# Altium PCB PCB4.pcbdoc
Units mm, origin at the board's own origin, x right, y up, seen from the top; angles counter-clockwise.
Board outline 77.7 x 78.7 mm, 4 copper layers (Top Layer, GND, VCC, Bottom Layer); 33 components, 18 nets, 107 pads, 174 vias.
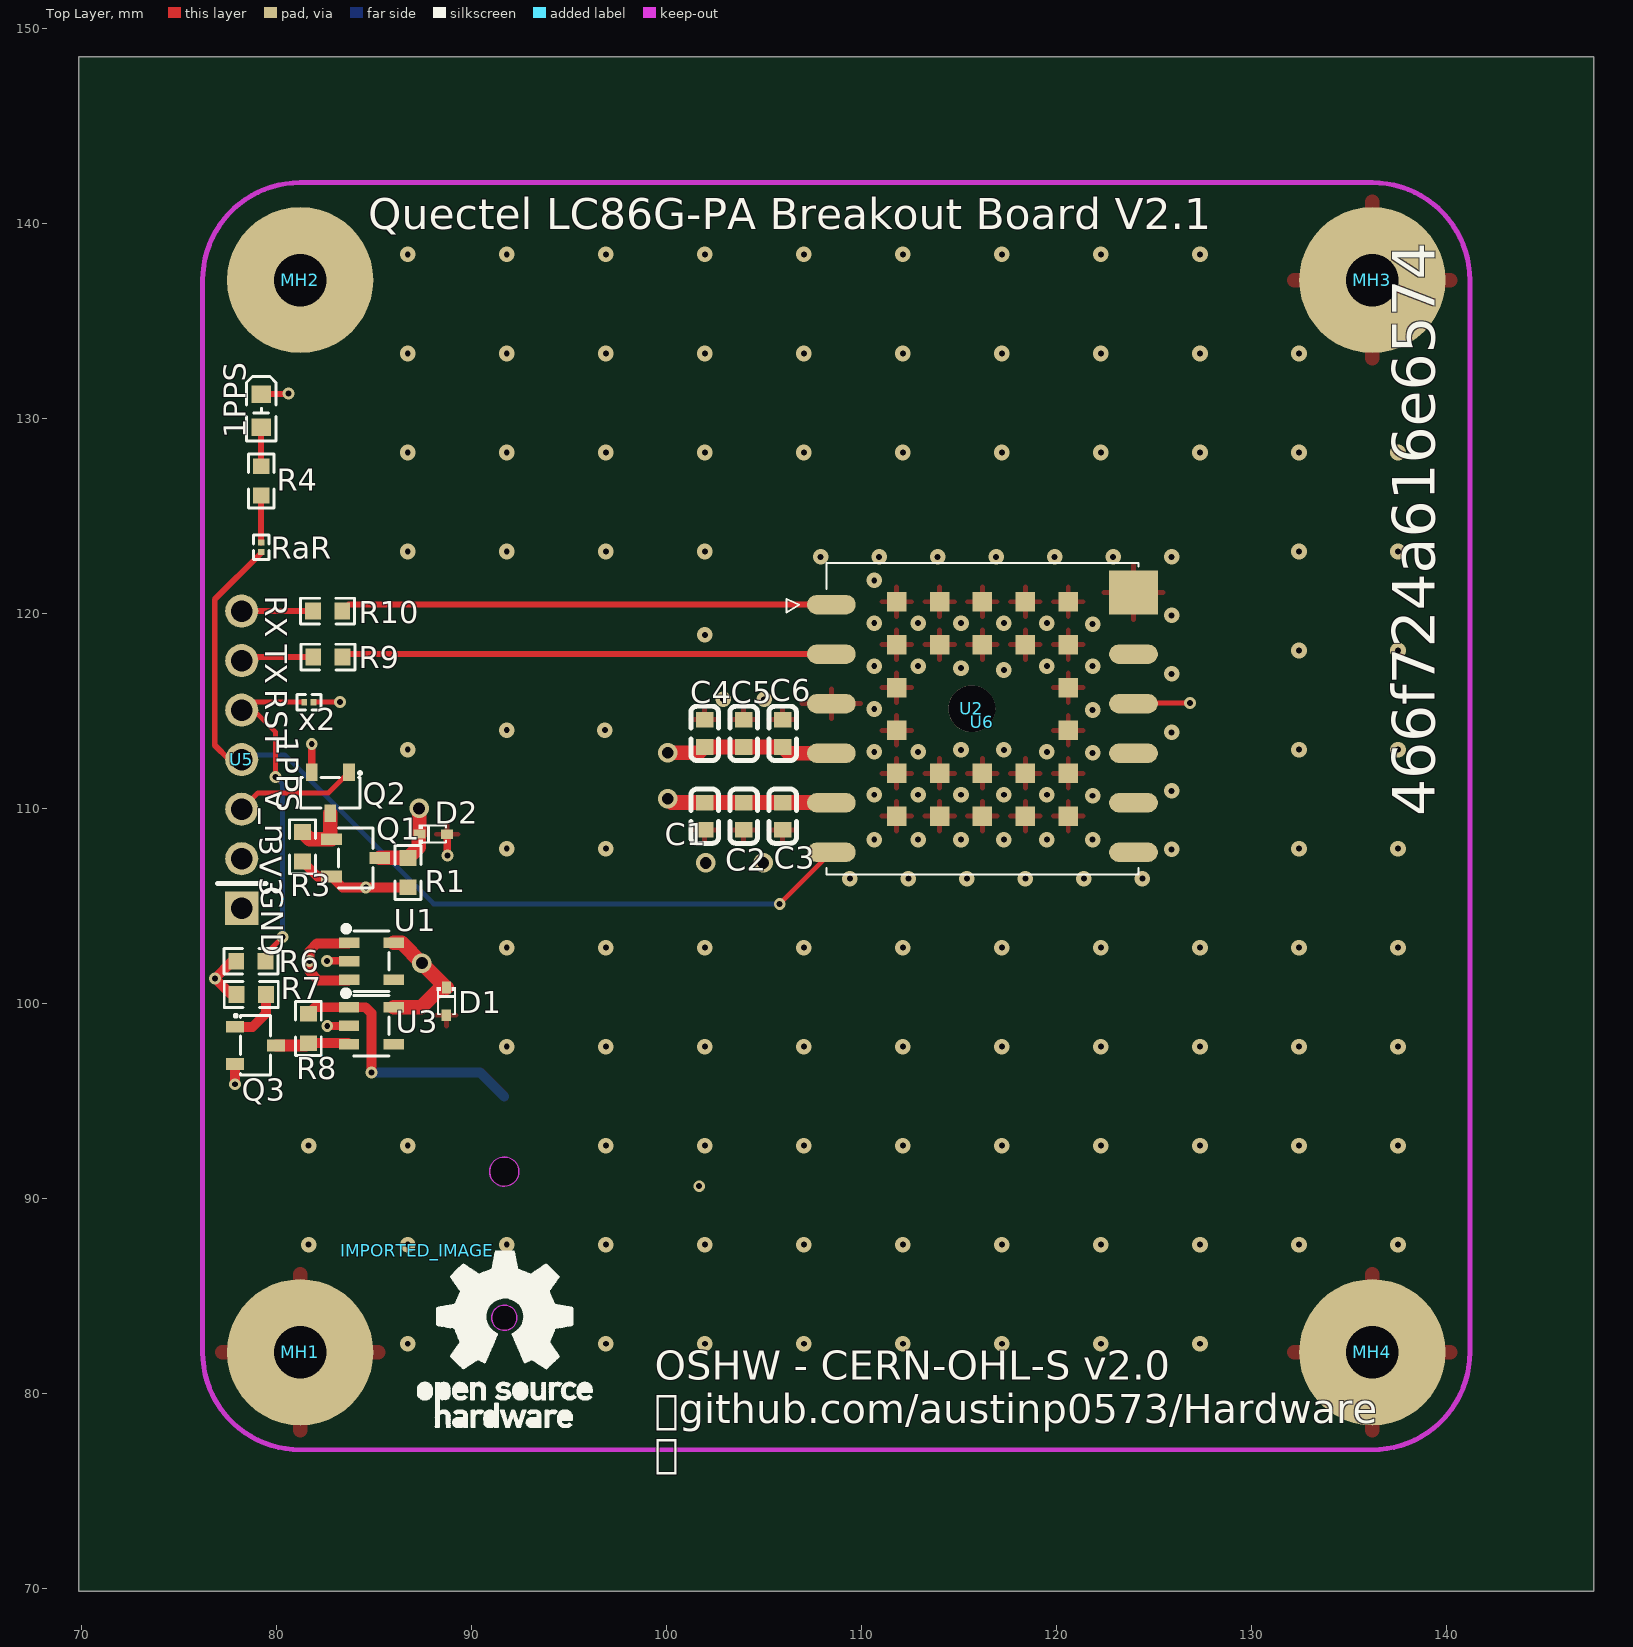
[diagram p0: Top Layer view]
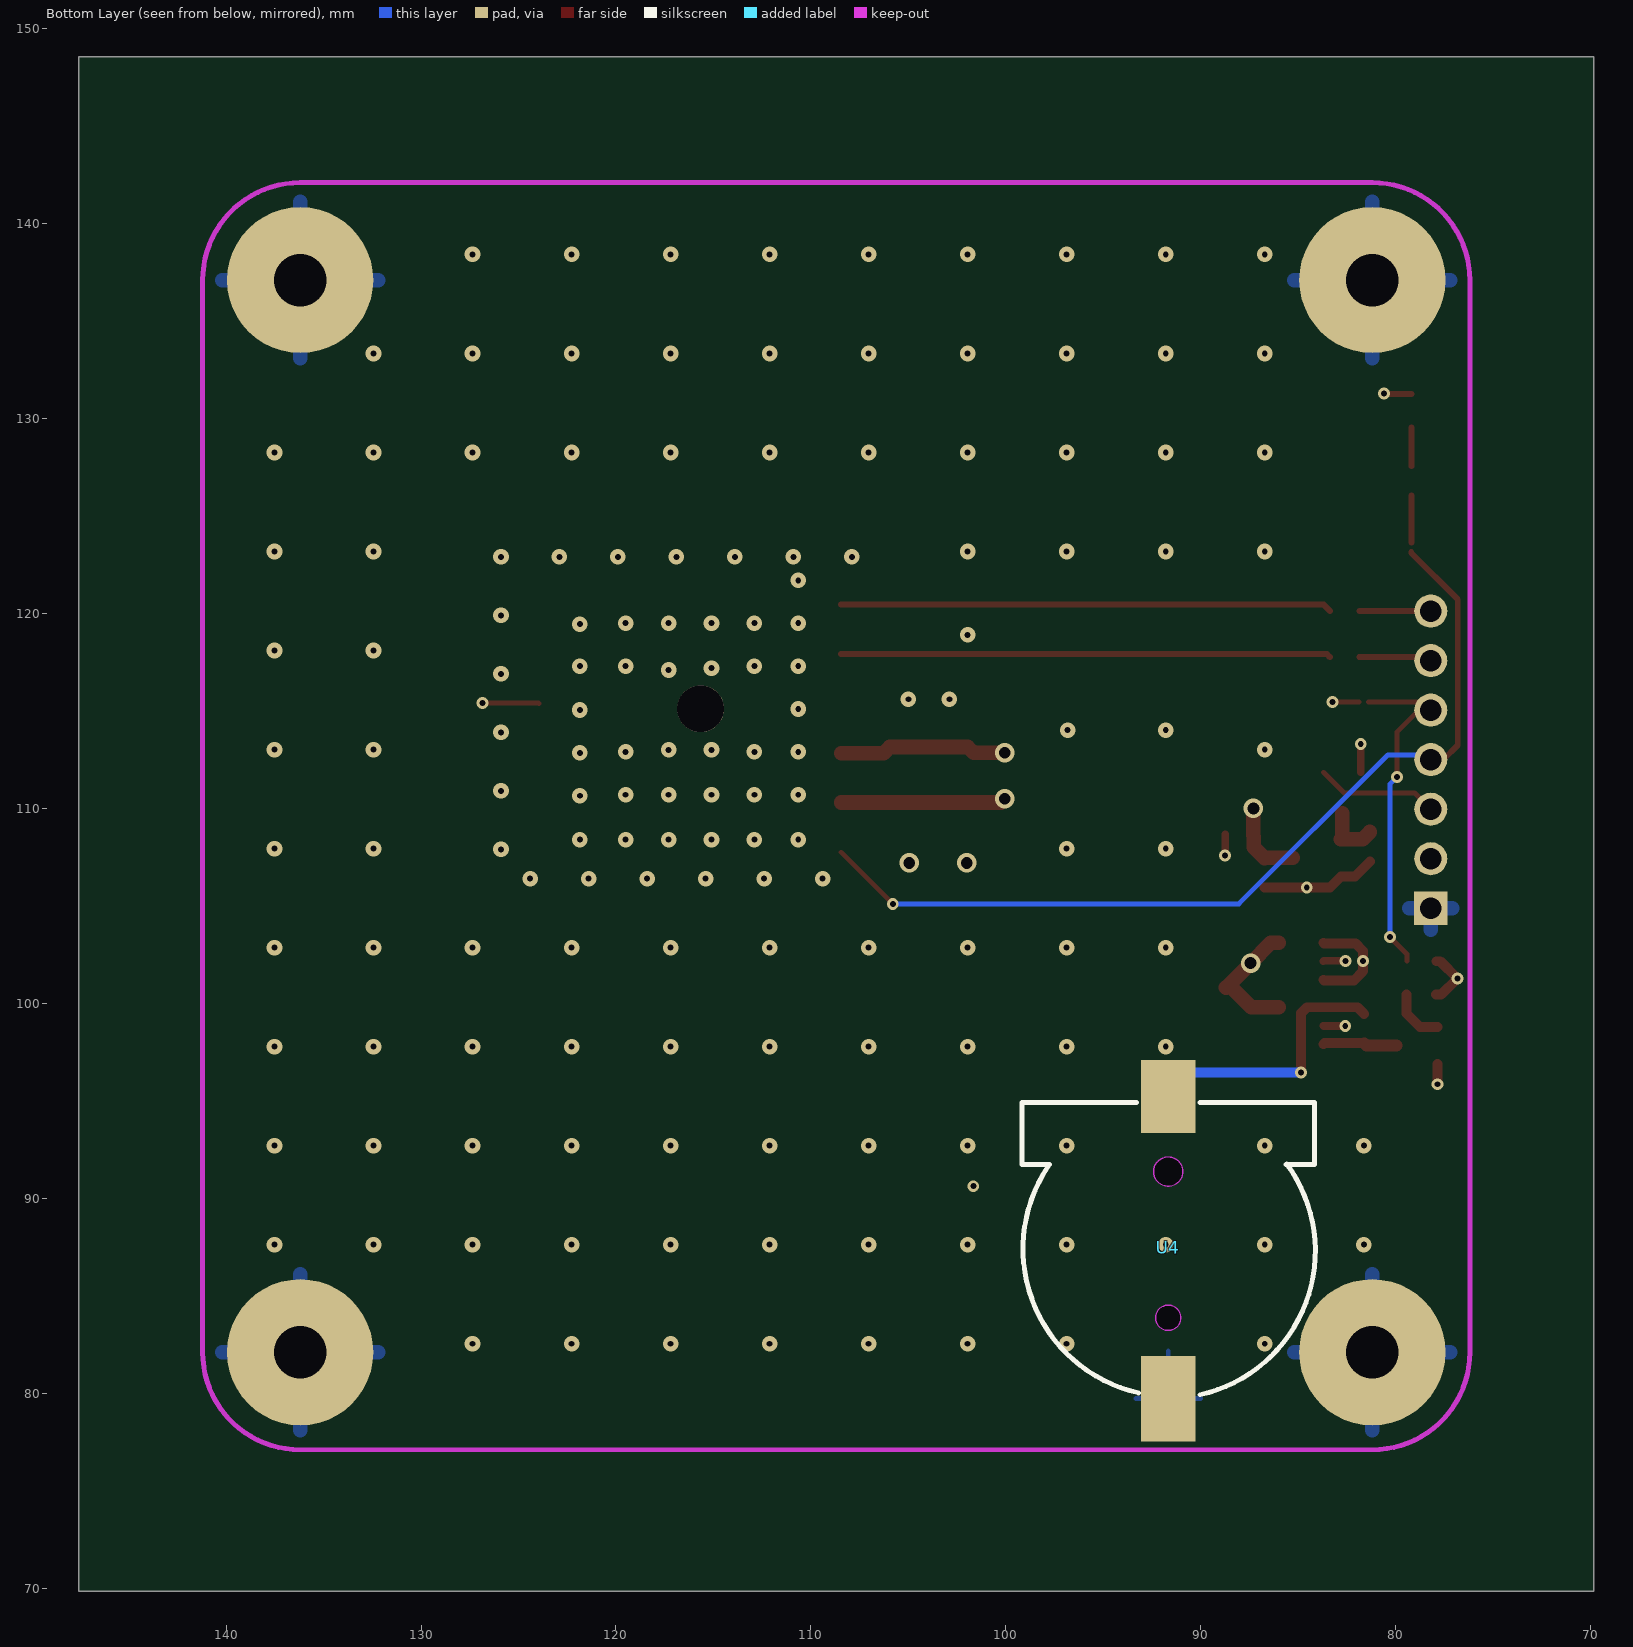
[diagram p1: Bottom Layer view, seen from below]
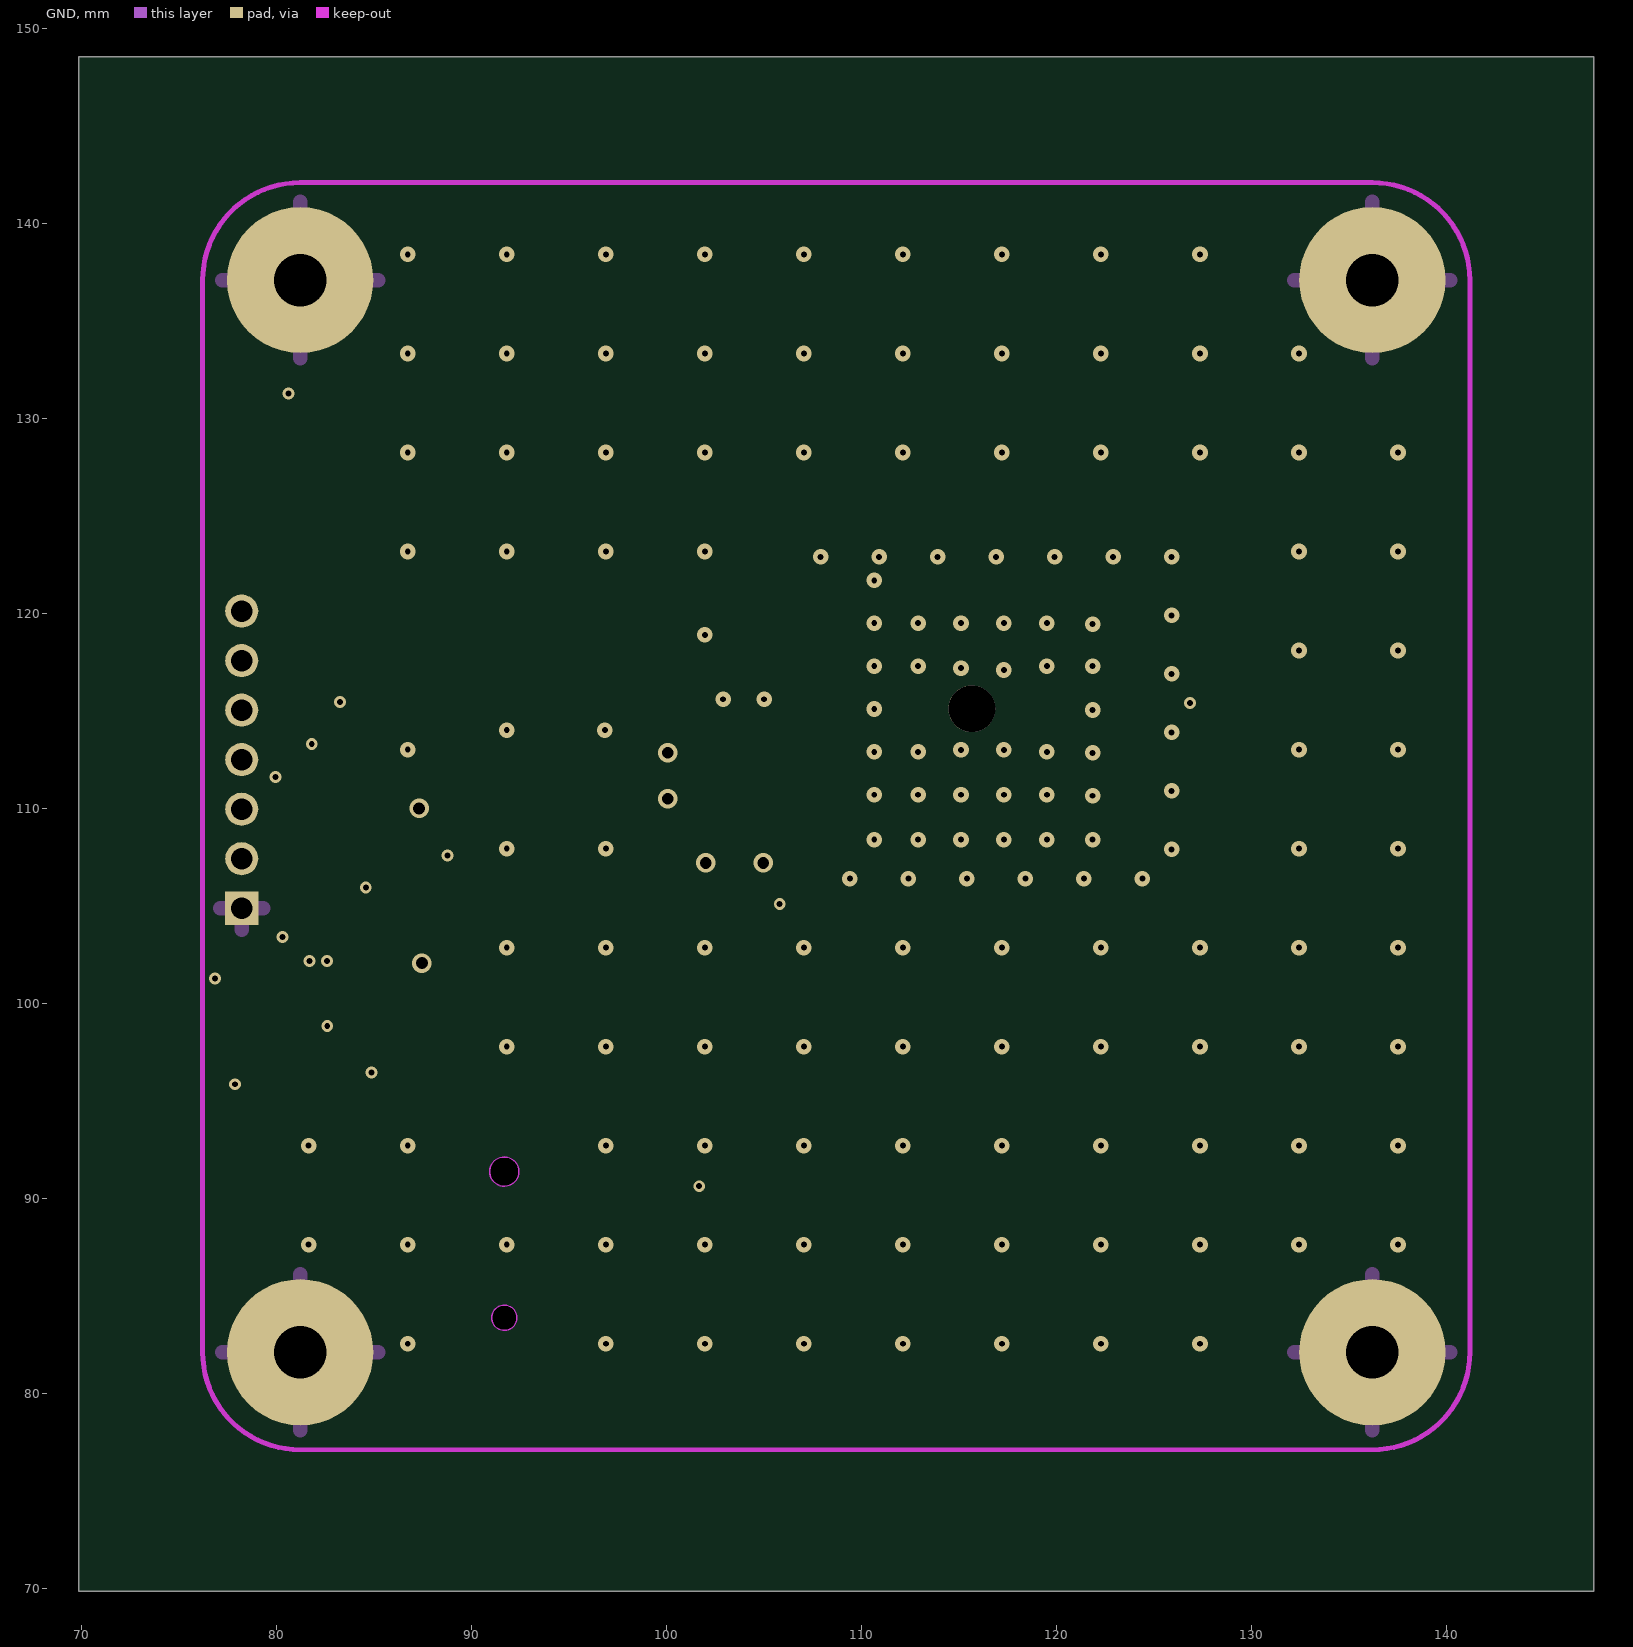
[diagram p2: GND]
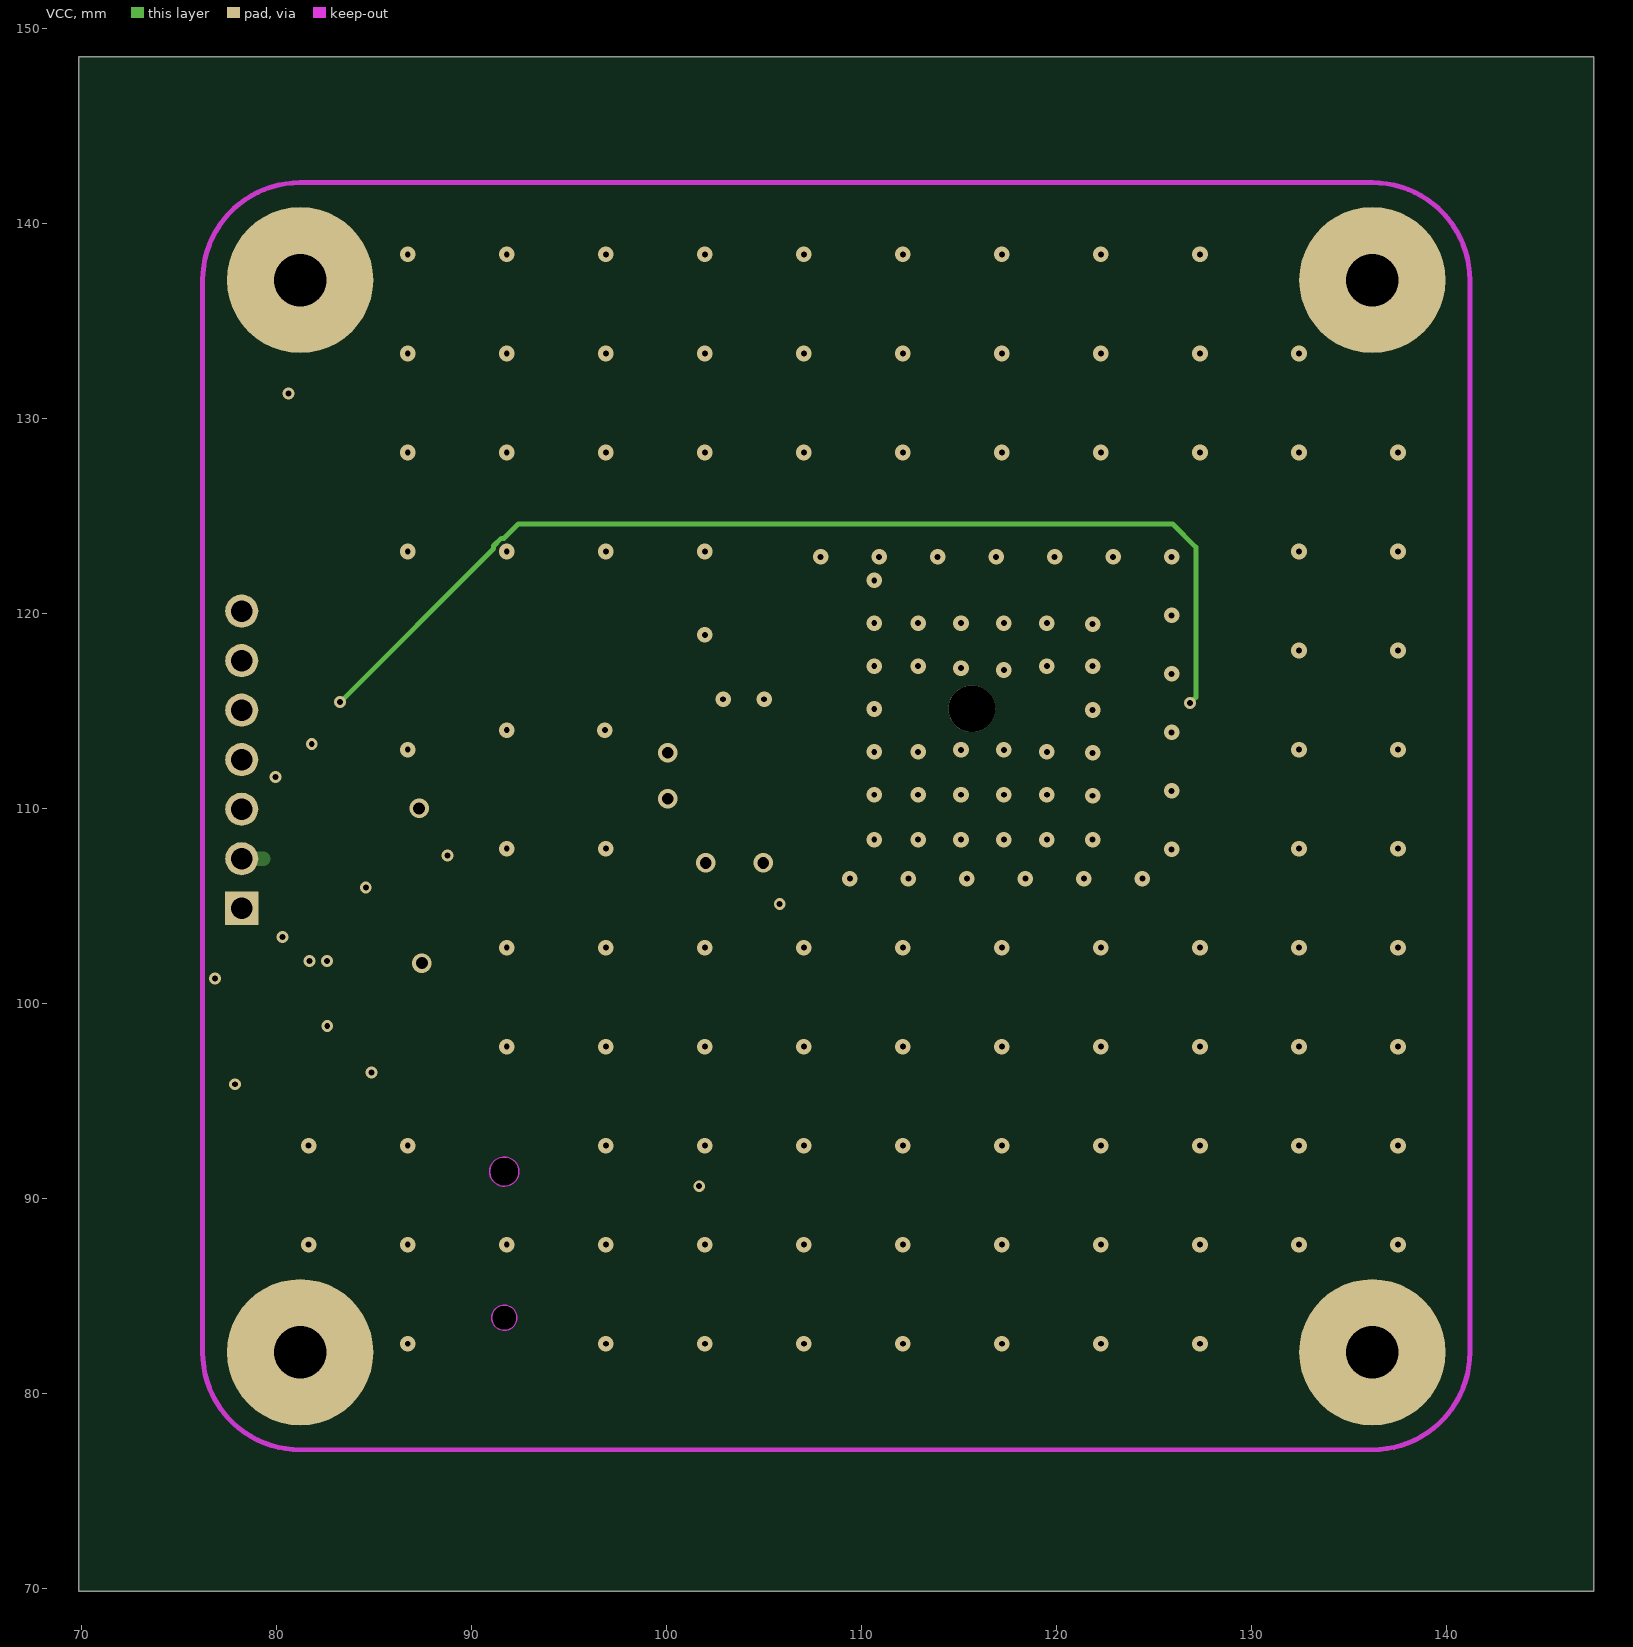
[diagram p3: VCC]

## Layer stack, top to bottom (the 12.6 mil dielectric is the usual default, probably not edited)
Top Layer: signal copper (thickness not stored)
Dielectric: dielectric 0.32, FR-4, Dk 4.8
GND: signal copper (thickness not stored)
Dielectric: dielectric 0.32, FR-4, Dk 4.8
VCC: signal copper (thickness not stored)
Dielectric: dielectric 0.32, FR-4, Dk 4.8
Bottom Layer: signal copper (thickness not stored)

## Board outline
147.55,69.85 69.85,69.85 69.85,148.55 147.55,148.55

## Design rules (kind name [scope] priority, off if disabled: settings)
BoardOutlineClearance copperThickness1oz [All] p0: genericclearance=0.254 ignorepadtopadclearanceinfootprint=FALSE except(0: Arc-SplitContinuation Track-SplitContinuation SMDPad-SplitContinuation THPad-SplitContinuation Via-SplitContinuation Fill-SplitContinuation Poly-SplitContinuation Region-SplitContinuation Text-SplitContinuation; 0.152: SMDPad-CutoutEdge THPad-CutoutEdge Via-CutoutEdge Fill-CutoutEdge Region-CutoutEdge; 0.3: Track-OutlineEdge SMDPad-OutlineEdge THPad-OutlineEdge Via-OutlineEdge Fill-OutlineEdge Region-OutlineEdge Poly-OutlineEdge Text-OutlineEdge Track-CutoutEdge)
BoardOutlineClearance copperThickness2oz [All] p0: genericclearance=0.254 ignorepadtopadclearanceinfootprint=FALSE except(0: Arc-SplitContinuation Track-SplitContinuation SMDPad-SplitContinuation THPad-SplitContinuation Via-SplitContinuation Fill-SplitContinuation Poly-SplitContinuation Region-SplitContinuation Text-SplitContinuation; 0.152: SMDPad-CutoutEdge THPad-CutoutEdge Via-CutoutEdge Fill-CutoutEdge Region-CutoutEdge; 0.3: Track-OutlineEdge SMDPad-OutlineEdge THPad-OutlineEdge Via-OutlineEdge Fill-OutlineEdge Region-OutlineEdge Poly-OutlineEdge Text-OutlineEdge Track-CutoutEdge)
BoardOutlineClearance copperThicknessInner0.5oz [All] p0: genericclearance=0.254 ignorepadtopadclearanceinfootprint=FALSE except(0: Arc-SplitContinuation Track-SplitContinuation SMDPad-SplitContinuation THPad-SplitContinuation Via-SplitContinuation Fill-SplitContinuation Poly-SplitContinuation Region-SplitContinuation Text-SplitContinuation; 0.152: SMDPad-CutoutEdge THPad-CutoutEdge Via-CutoutEdge Fill-CutoutEdge Region-CutoutEdge; 0.3: Track-OutlineEdge SMDPad-OutlineEdge THPad-OutlineEdge Via-OutlineEdge Fill-OutlineEdge Region-OutlineEdge Poly-OutlineEdge Text-OutlineEdge Track-CutoutEdge)
Clearance copperThickness1oz [(InNet('V_BCKP') OR InNet('GND') OR InNet('VCC_MODULE_3.3V') OR InNet('$1N11305') OR InNet('$1N4698') OR InNet('VCC_MCU_3.3V') OR InNet('VCC_EN') OR InNet('$1N8070') OR InNet('$1N8139') OR InNet('1PPS') OR InNet('$1N11301') OR InNet('GPIO_RESET') OR InNet('RESET_N') OR InNet('$1N2567') OR InNet('RXD_MCU') OR InNet('TXD') OR InNet('TXD_MCU') OR InNet('RXD'))] p1: gap=0.178 ignorepadtopadclearanceinfootprint=FALSE except(0.102: Track-Track; 0.152: Track-SMDPad SMDPad-SMDPad Track-THPad SMDPad-THPad THPad-THPad Track-Via SMDPad-Via THPad-Via Via-Via Track-Fill SMDPad-Fill THPad-Fill Via-Fill Fill-Fill SMDPad-Region THPad-Region Via-Region Fill-Region Region-Region Track-Poly SMDPad-Poly THPad-Poly Via-Poly Fill-Poly Poly-Poly Track-Text SMDPad-Text THPad-Text Via-Text Fill-Text Region-Text Poly-Text Text-Text; 0.175: Track-Hole SMDPad-Hole THPad-Hole Via-Hole Fill-Hole Region-Hole Poly-Hole Text-Hole Sheet-Hole; 0.3: Track-Region Region-Poly Track-Sheet SMDPad-Sheet THPad-Sheet Via-Sheet Fill-Sheet Region-Sheet Poly-Sheet Text-Sheet)
Clearance copperThickness2oz [All] p1: gap=0.178 ignorepadtopadclearanceinfootprint=FALSE except(0.152: Track-SMDPad SMDPad-SMDPad Track-THPad SMDPad-THPad THPad-THPad Track-Via SMDPad-Via THPad-Via Via-Via Track-Fill SMDPad-Fill THPad-Fill Via-Fill Fill-Fill SMDPad-Region THPad-Region Via-Region Fill-Region Region-Region Track-Poly SMDPad-Poly THPad-Poly Via-Poly Fill-Poly Poly-Poly Track-Text SMDPad-Text THPad-Text Via-Text Fill-Text Region-Text Poly-Text Text-Text; 0.175: Track-Hole SMDPad-Hole THPad-Hole Via-Hole Fill-Hole Region-Hole Poly-Hole Text-Hole Sheet-Hole; 0.203: Track-Track; 0.3: Track-Region Region-Poly Track-Sheet SMDPad-Sheet THPad-Sheet Via-Sheet Fill-Sheet Region-Sheet Poly-Sheet Text-Sheet)
Clearance copperThicknessInner0.5oz [All] p1: gap=0.178 ignorepadtopadclearanceinfootprint=FALSE except(0.089: Track-Track; 0.152: Track-SMDPad SMDPad-SMDPad Track-THPad SMDPad-THPad THPad-THPad Track-Via SMDPad-Via THPad-Via Via-Via Track-Fill SMDPad-Fill THPad-Fill Via-Fill Fill-Fill SMDPad-Region THPad-Region Via-Region Fill-Region Region-Region Track-Poly SMDPad-Poly THPad-Poly Via-Poly Fill-Poly Poly-Poly Track-Text SMDPad-Text THPad-Text Via-Text Fill-Text Region-Text Poly-Text Text-Text; 0.175: Track-Hole SMDPad-Hole THPad-Hole Via-Hole Fill-Hole Region-Hole Poly-Hole Text-Hole Sheet-Hole; 0.3: Track-Region Region-Poly Track-Sheet SMDPad-Sheet THPad-Sheet Via-Sheet Fill-Sheet Region-Sheet Poly-Sheet Text-Sheet)
DiffPairsRouting differentialPair [All] p1: maxuncoupledlength=10 minlimit=5.9843 maxlimit=5.9843 mostfreqgap=5.9843 toplayer_minwidth=5 toplayer_prefwidth=10 toplayer_maxwidth=100 bottomlayer_minwidth=5 bottomlayer_prefwidth=10 bottomlayer_maxwidth=100 midlayer1_minwidth=5 midlayer1_prefwidth=10 midlayer1_maxwidth=100 midlayer2_minwidth=5 midlayer2_prefwidth=10 midlayer2_maxwidth=100
PasteMaskExpansion pasteMaskExpansion [All] p1: expansion=0
PlaneConnect innerPlane [All] p1: planeconnectstyle=Relief reliefexpansion=0.508 reliefentries=4 reliefconductorwidth=0.254 reliefairgap=0.254
PolygonConnect copperRegion [All] p1: connectstyle=Relief reliefentries=4 reliefconductorwidth=10 polygonreliefangle="90 Angle" airgapwidth=10
RoutingVias viaSize [All] p1: viastyle="Through Hole" holewidth=12.0078 minholewidth=7.874 maxholewidth=248.0314 width=24.0158 minwidth=11.811 maxwidth=393.7008
SolderMaskExpansion solderMaskExpansion [All] p1: useseparateexpansions=TRUE expansion=2.0079 expansionbottom=2.0079
Width copperThickness1oz [All] p1: maxlimit=100 minlimit=4 preferedwidth=10
Width copperThickness2oz [All] p1: maxlimit=100 minlimit=8 preferedwidth=10
Width copperThickness0.5oz [All] p1: maxlimit=100 minlimit=4 preferedwidth=10

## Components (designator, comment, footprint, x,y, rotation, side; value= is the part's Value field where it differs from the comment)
1PPS "" LED0603-FD 79.2,130.4 r90 top
C1 "" C0603 101.95,109.6 r90 top
C2 "" C0603 103.95,109.6 r90 top
C3 "" C0603 105.95,109.6 r90 top
C4 "" C0603 101.95,113.85 r270 top
C5 "" C0603 103.95,113.85 r270 top
C6 "" C0603 105.95,113.85 r270 top
D1 "" SOD-523F_L1.2-W0.8-LS1.7-RD 88.7,100.1 r270 top
D2 "" SOD-523F_L1.2-W0.8-LS1.7-RD 88.03,108.68 r0 top
IMPORTED_IMAGE "IMPORTED_IMAGE" IMPORTED_IMAGE 87.2,87.3 r0 top
MH1 "" MH_7.5x2.7MM 81.2,82.1 r0 top
MH2 "" MH_7.5x2.7MM 81.2,137.1 r0 top
MH3 "" MH_7.5x2.7MM 136.2,137.1 r0 top
MH4 "" MH_7.5x2.7MM 136.2,82.1 r0 top
Q1 "" SOT-23-3_L2.9-W1.6-P1.90-LS2.8-BR 84.05,107.46 r180 top
Q2 "" SOT-23-3_L2.9-W1.4-P1.90-LS2.6-BR 82.75,110.8 r90 top
Q3 "" SOT-23-3_L2.9-W1.4-P1.90-LS2.6-BR 78.91,97.84 r180 top
R1 "" R0603 86.733,106.703 r270 top
R3 "" R0603 81.323,108.033 r270 top
R4 "" R0603 79.2,126.8 r270 top
R6 "" R0603 78.67,102.16 r0 top
R7 "" R0603 78.69,100.45 r0 top
R8 "" R0603 81.62,98.71 r270 top
R9 "" R0603 82.623,117.76 r180 top
R10 "" R0603 82.61,120.12 r180 top
RaR "" R0201 79.2,123.4 r270 top
U1 "" TSOT-23-5_L2.9-W1.6-P0.95-LS2.8-BL 84.86,102.16 r270 top
U2 "" "KEEPOUT HOLEf" 115.657,115.117 r0 top
U3 "" TSOT-23-5_L2.9-W1.6-P0.95-LS2.8-BL 84.85,98.85 r270 top
U4 "CR1225_BATTERY_HOLDER" BAT-SMD_BS-12-B3AA011 91.67,87.47 r90 bottom
U5 "MALE_HEADER_7X1" HDR-TH_7P-P2.54-V-M 78.2,112.5 r90 top
U6 "" LC86G 116.2,114.6 r0 top
x2 "" R0201 81.65,115.45 r180 top

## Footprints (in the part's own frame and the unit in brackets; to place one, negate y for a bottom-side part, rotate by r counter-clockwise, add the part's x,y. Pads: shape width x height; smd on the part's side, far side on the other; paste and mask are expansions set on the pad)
BAT-SMD_BS-12-B3AA011 [mm]
  rect 3.75x2.8 smd: 1(7.75,0)
  rect 4.4x2.8 smd: 2(-7.75,0)
  Board Outline Layer circle w0.005: c-3.6,0 r0.65
  Board Outline Layer circle w0.005: c3.9,0 r0.75
  Board Outline Layer region: -3.6,0.65 -3.882,0.586 -4.108,0.405 -4.234,0.145 -4.234,-0.145 -4.108,-0.405 -3.882,-0.586 -3.6,-0.65 -3.6,-0.65 -3.318,-0.586 -3.092,-0.405 -2.966,-0.145 -2.966,0.145 -3.092,0.405 -3.318,0.586 -3.6,0.65
  Board Outline Layer region: 3.9,0.75 3.575,0.676 3.314,0.468 3.169,0.167 3.169,-0.167 3.314,-0.468 3.575,-0.676 3.9,-0.75 3.9,-0.75 4.225,-0.676 4.486,-0.468 4.631,-0.167 4.631,0.167 4.486,0.468 4.225,0.676 3.9,0.75
  Multi-Layer board cut-out: -3.6,0.65 -3.882,0.586 -4.108,0.405 -4.234,0.145 -4.234,-0.145 -4.108,-0.405 -3.882,-0.586 -3.6,-0.65 -3.6,-0.65 -3.318,-0.586 -3.092,-0.405 -2.966,-0.145 -2.966,0.145 -3.092,0.405 -3.318,0.586 -3.6,0.65
  Multi-Layer board cut-out: 3.9,0.75 3.575,0.676 3.314,0.468 3.169,0.167 3.169,-0.167 3.314,-0.468 3.575,-0.676 3.9,-0.75 3.9,-0.75 4.225,-0.676 4.486,-0.468 4.631,-0.167 4.631,0.167 4.486,0.468 4.225,0.676 3.9,0.75
  silkscreen extent -7.55,-7.54 7.44,7.49
C0603 [mm]
  rect 0.8x0.9 smd: 1(-0.7,0) 2(0.7,0)
  silkscreen extent -1.39,-0.71 1.39,0.71
HDR-TH_7P-P2.54-V-M [mm]
  rect 1.7x1.7 hole 1.1: 1(-7.62,0)
  round 1.7 hole 1.1: 2(-5.08,0) 3(-2.54,0) 4(0,0) 5(2.54,0) 6(5.08,0) 7(7.62,0)
  silkscreen extent -6.35,-1.25 -6.35,1.25
IMPORTED_IMAGE [mm]
  silkscreen extent 0,-9.08 9,0
"KEEPOUT HOLEf" [mm]
  round 2.4 hole 2.4 unplated: 1(0,0)
LC86G [mm]
  oval 2.5x1 smd: 1(-7.75,5.85) 2(-7.75,3.31) 3(-7.75,0.77) 4(-7.75,-1.77) 5(-7.75,-4.31) 6(-7.75,-6.85) 7(7.75,-6.85) 8(7.75,-4.31) 9(7.75,-1.77) 10(7.75,0.77) 11(7.75,3.31)
  rect 2.5x2.25 smd: 12(7.75,6.475)
  rect 1x1 smd: 13(-4.4,6) 14(-2.2,6) 15(0,6) 16(2.2,6) 17(4.4,6) 18(-4.4,3.8) 19(-2.2,3.8) 20(0,3.8) 21(2.2,3.8) 22(4.4,3.8) 23(-4.4,1.6) 24(4.4,1.6) 25(-4.4,-0.6) 26(4.4,-0.6) 27(-4.4,-2.8) 28(-2.2,-2.8) 29(0,-2.8) 30(2.2,-2.8) 31(4.4,-2.8) 32(-4.4,-5) 33(-2.2,-5) 34(0,-5) 35(2.2,-5) 36(4.4,-5)
  silkscreen extent -10.05,-8 8,8
LED0603-FD [mm]
  rect 0.9x1 smd: 1(-0.85,0) 2(0.85,0)
  silkscreen extent -1.55,-0.75 1.75,0.75
MH_7.5x2.7MM [mm]
  round 7.5 hole 2.7: 1(0,0)
R0201 [mm]
  rect 0.303x0.324 smd: 1(-0.242,0) 2(0.242,0)
  silkscreen extent -0.62,-0.39 0.62,0.39
R0603 [mm]
  rect 0.806x0.864 smd: 1(-0.753,0) 2(0.753,0)
  silkscreen extent -1.39,-0.66 1.39,0.66
SOD-523F_L1.2-W0.8-LS1.7-RD [mil]
  rect 24x19 smd: 1(-28,0.2) 2(28,-0.2)
  silkscreen extent -29,-19 26,19
SOT-23-3_L2.9-W1.4-P1.90-LS2.6-BR [mm]
  rect 0.91x0.6 smd: 1(1.055,-0.955) 2(1.055,0.955) 3(-1.055,0)
  silkscreen extent -0.78,-1.6 1.09,1.53
SOT-23-3_L2.9-W1.6-P1.90-LS2.8-BR [mm]
  rect 1.07x0.6 smd: 1(1.235,-0.95) 2(1.235,0.95) 3(-1.235,0)
  silkscreen extent -0.88,-1.54 0.88,1.54
TSOT-23-5_L2.9-W1.6-P0.95-LS2.8-BL [mm]
  rect 0.532x1.045 smd: 1(-0.95,-1.148) 2(0,-1.148) 3(0.95,-1.148) 4(0.95,1.148) 5(-0.95,1.148)
  silkscreen extent -1.82,-1.45 1.55,0.9

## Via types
v1: diameter 0.8, hole 0.305, Top Layer to Bottom Layer, 152 vias
v2: diameter 0.61, hole 0.305, Top Layer to Bottom Layer, 16 vias
v3: diameter 1, hole 0.6, Top Layer to Bottom Layer, 6 vias

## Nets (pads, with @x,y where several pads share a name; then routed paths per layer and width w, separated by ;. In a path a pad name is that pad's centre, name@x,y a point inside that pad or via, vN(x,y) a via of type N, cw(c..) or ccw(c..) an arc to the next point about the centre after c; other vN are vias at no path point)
1PPS: RaR.2 U5.4 U6.6 | length 47
  Top Layer w0.254: v2(105.8,105.1) U6.6
  Top Layer w0.3: U5.4@78,112.5 77.996,112.504 77.549,112.504 76.819,113.234 76.819,120.723 79.2,123.103 RaR.2
  Bottom Layer w0.254: U5.4 78.45,112.75 80.4,112.75 88.05,105.1 v2(105.8,105.1)
$1N2567: R8.1 U3.1 U4.1 | length 13.9
  Top Layer w0.508: R8.1 81.957,99.8 U3.1 84.55,99.8 84.85,99.5 v2(84.85,96.45)
  Bottom Layer w0.508: v2(84.85,96.45) 90.44,96.45 U4.1
$1N4698: Q1.1 Q2.3 R3.1 | length 3
  Top Layer w0.75: R3.1 81.7,108.41 Q1.1 82.75,108.475 Q2.3
$1N8070: Q3.1 R7.2 | length 2.8
  Top Layer w0.508: Q3.1 78.755,98.795 79.443,99.483 R7.2
$1N8139: Q3.3 R8.2 U3.3 | length 3.8
  Top Layer w0.508: R8.2 83.646,97.957 U3.3
  Top Layer w0.6: Q3.3 81.503,97.84 R8.2
$1N11301: R4.2 RaR.1 | length 2.4
  Top Layer w0.305: RaR.1 R4.2
$1N11305: 1PPS.1 R4.1 | length 2
  Top Layer w0.305: R4.1 1PPS.1
GND: 1PPS.2 C1.1 C2.1 C3.1 C4.1 C5.1 C6.1 D1.2 D2.2 MH1.1 MH2.1 MH3.1 MH4.1 Q2.2 Q3.2 U1.2 U3.2 U4.2 U5.1 U6.3 U6.12 U6.13 U6.14 U6.15 U6.16 U6.17 U6.18 U6.19 U6.20 U6.21 U6.22 U6.23 U6.24 U6.25 U6.26 U6.27 U6.28 U6.29 U6.30 U6.31 U6.32 U6.33 U6.34 U6.35 U6.36 | length 7.3
  Top Layer w0.305: 1PPS.2 80.58,131.25 v2(80.61,131.28)
  Top Layer w0.399: Q2.2 v2(81.795,113.304) ; v2(82.58,102.18) 83.692,102.18 U1.2 ; v2(82.59,98.84) 83.692,98.84 U3.2 ; D2.2 88.741,107.589 v2(88.75,107.58)
  Top Layer w0.508: v2(77.85,95.85) 77.855,95.855 Q3.2
  other v1: 86.718,82.538 96.878,82.538 101.958,82.538 107.038,82.538 112.118,82.538 117.198,82.538 122.278,82.538 127.358,82.538 81.638,87.618 86.718,87.618 91.798,87.618 96.878,87.618 101.958,87.618 107.038,87.618 112.118,87.618 117.198,87.618 122.278,87.618 127.358,87.618 132.438,87.618 137.518,87.618 81.638,92.698 86.718,92.698 96.878,92.698 101.958,92.698 107.038,92.698 112.118,92.698 117.198,92.698 122.278,92.698 127.358,92.698 132.438,92.698 137.518,92.698 91.798,97.778 96.878,97.778 101.958,97.778 107.038,97.778 112.118,97.778 117.198,97.778 122.278,97.778 127.358,97.778 132.438,97.778 137.518,97.778 91.798,102.858 96.878,102.858 101.958,102.858 107.038,102.858 112.118,102.858 117.198,102.858 122.278,102.858 127.358,102.858 132.438,102.858 137.518,102.858 109.4,106.4 112.4,106.4 115.4,106.4 118.4,106.4 121.4,106.4 124.4,106.4 125.9,107.9 91.798,107.938 96.878,107.938 132.438,107.938 137.518,107.938 110.65,108.4 112.9,108.4 115.1,108.4 117.3,108.4 119.5,108.4 121.85,108.4 121.85,110.65 110.65,110.7 112.9,110.7 115.1,110.7 117.3,110.7 119.5,110.7 125.9,110.9 121.85,112.85 110.65,112.9 112.9,112.9 119.5,112.9 115.1,113 117.3,113 86.718,113.018 132.438,113.018 137.518,113.018 125.9,113.9 91.798,114.018 96.828,114.018 121.85,115.05 110.65,115.1 102.9,115.6 105,115.6 125.9,116.9 117.3,117.1 115.1,117.2 110.65,117.3 112.9,117.3 119.5,117.3 121.85,117.3 132.438,118.098 137.518,118.098 101.958,118.898 121.85,119.45 110.65,119.5 112.9,119.5 115.1,119.5 117.3,119.5 119.5,119.5 125.9,119.9 110.65,121.7 107.9,122.9 110.9,122.9 113.9,122.9 116.9,122.9 119.9,122.9 122.9,122.9 125.9,122.9 86.718,123.178 91.798,123.178 96.878,123.178 101.958,123.178 132.438,123.178 137.518,123.178 86.718,128.258 91.798,128.258 96.878,128.258 101.958,128.258 107.038,128.258 112.118,128.258 117.198,128.258 122.278,128.258 127.358,128.258 132.438,128.258 137.518,128.258 86.718,133.338 91.798,133.338 96.878,133.338 101.958,133.338 107.038,133.338 112.118,133.338 117.198,133.338 122.278,133.338 127.358,133.338 132.438,133.338 86.718,138.418 91.798,138.418 96.878,138.418 101.958,138.418 107.038,138.418 112.118,138.418 117.198,138.418 122.278,138.418 127.358,138.418
  other v3: 102,107.2 104.95,107.2
GPIO_RESET: R6.2 U5.5 x2.2 | length 17.8
  Top Layer w0.254: R6.2 79.423,102.523 v2(80.3,103.4) ; v2(79.926,111.618) 79.926,113.924 78.81,115.04 U5.5 78.61,115.45 x2.2
  Bottom Layer w0.254: v2(79.926,111.618) 80.3,111.243 v2(80.3,103.4)
RESET_N: U6.10 x2.1 | length 60.7
  Top Layer w0.254: x2.1 v2(83.25,115.45) ; U6.10 123.98,115.4 v2(126.85,115.4)
  VCC w0.254: v2(83.25,115.45) 91.119,123.319 91.119,123.459 91.517,123.857 91.657,123.857 92.4,124.6 125.95,124.6 127.15,123.4 127.15,115.7 v2(126.85,115.4)
RXD: R10.1 U6.1 | length 25.2
  Top Layer w0.305: R10.1 83.693,120.45 U6.1
RXD_MCU: R9.2 U5.6 | length 3.7
  Top Layer w0.305: U5.6 78.38,117.76 R9.2
TXD: R9.1 U6.2 | length 25.1
  Top Layer w0.305: R9.1 83.527,117.91 U6.2
TXD_MCU: R10.2 U5.7 | length 3.7
  Top Layer w0.305: U5.7 R10.2
V_BCKP: C1.2 C2.2 C3.2 D1.1 U1.5 U3.5 U6.5 | length 15
  Top Layer w0.75: U3.5 87.41,99.8 D1.1@88.471,100.861 ; U1.5 86.406,103.11 v3(87.448,102.068) D1.1 ; v3(100.05,110.5) 100.25,110.3 C1.2 C2.2 C3.2 108.44,110.3 U6.5
VCC_EN: Q2.1 U5.3 | length 6.3
  Top Layer w0.254: U5.3 79.04,110.8 82.65,110.8 Q2.1
VCC_MCU_3.3V: Q1.2 R1.2 R3.2 R6.1 R7.1 U1.1 U1.3 U5.2 | length 14.4
  Top Layer w0.508: R6.1 77.714,102.16 v2(76.836,101.281) 77.667,100.45 R7.1 ; R3.2 82.093,106.51 Q1.2 83.375,105.95 v2(84.566,105.95) R1.2 ; U1.3 83.682,101.18 82.14,101.18 81.67,101.65 v2(81.67,102.168) 81.67,102.69 82.06,103.08 83.682,103.08 U1.1
VCC_MODULE_3.3V: C4.2 C5.2 C6.2 D2.1 Q1.3 R1.1 U6.4 | length 12.8
  Top Layer w0.75: Q1.3 86.73,107.46 R1.1 87.283,108.006 D2.1@87.283,108.533 ; v3(87.3,110) 87.3,108.625 D2.1@87.304,108.621 ; v3(100.05,112.85) 101.65,112.85 C4.2 C5.2 C6.2 106.27,112.83 U6.4
pads on no net: U1.4 U2.1 U3.4 U6.7 U6.8 U6.9 U6.11
copper on no net:
  other v2: 101.67,90.62

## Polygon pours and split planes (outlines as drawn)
GND on Bottom Layer (solid, remove dead copper, pour order 2): 81.2,142.2 136.2,142.2 cw(c136.2,137.2) 141.2,137.2 141.2,82.2 cw(c136.2,82.2) 136.2,77.2 81.2,77.2 cw(c81.2,82.2) 76.2,82.2 76.2,137.2 cw(c81.2,137.2)
GND on GND (solid, remove dead copper): 81.2,142.1 136.2,142.1 cw(c136.2,137.1) 141.2,137.1 141.2,82.1 cw(c136.2,82.1) 136.2,77.1 81.2,77.1 cw(c81.2,82.1) 76.2,82.1 76.2,137.1 cw(c81.2,137.1)
VCC_MCU_3.3V on VCC (solid, remove dead copper): 77.1,106.3 77.1,108.6 79.3,108.6 79.9,108 82.3,108 82.3,107.6 82.7,107.2 83.2,107.2 83.9,106.5 87.2,106.5 87.3,106.4 87.3,105.2 87.2,105.1 84.4,105.1 84.2,105.3 84.2,103.9 84.5,103.6 84.5,100.6 81.322,100.6 80.422,99.7 76.549,99.709 76.534,102.814 80.1,102.8 80.2,102.9 80.2,106.3
GND on Top Layer (solid, remove dead copper, pour order 0): 85.5,142.1 85.5,95.4 76.5,95.4 76.4,95.3 76.4,77.2 140.9,77.2 141.1,77.4 141.1,142 85.6,142
VCC_MODULE_3.3V on VCC (solid, remove dead copper): 84.65,107.15 84.65,108.6 86.697,108.6 86.697,113.403 86.6,113.5 106.233,113.5 106.33,113.403 106.33,112.22 106.35,112.2 87.7,112.2 87.65,112.15 87.65,107.25 87.55,107.15
V_BCKP on VCC (solid, remove dead copper): 85.5,102.35 85.5,103.9 91,103.9 98.2,111.1 98.2,111.15 109.527,111.15 109.55,110.1 98.8,110 89.9,100.95 89.75,100.95 89,101.7 87.35,101.7 86.75,102.3 86.75,102.35

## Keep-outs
Board Outline Layer:
  lines w0.254: 76.2,82.1 ccw(c81.2,82.1) 81.2,77.1 136.2,77.1 ccw(c136.2,82.1) 141.2,82.1 141.2,137.1 ccw(c136.2,137.1) 136.2,142.1 81.2,142.1 ccw(c81.2,137.1) 76.2,137.1 76.2,82.1

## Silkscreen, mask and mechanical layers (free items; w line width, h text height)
Top Silkscreen Layer:
  text "Quectel LC86G-PA Breakout Board V2.1" at 84.7,139.7 h1.6
  text "RX" at 79.4,120.9 h1.14 r270
  text "TX" at 79.4,118.4 h1.14 r270
  text "RST" at 79.4,116.1 h1.14 r270
  text "1PPS" at 80,113.7 h1.14 r270
  text "v_n" at 79.4,110.9 h1.14 r270
  text "466f724a616e6574" at 139.4,109.6 h2.2 r90
  text "3V3" at 79.129,108.543 h1.14 r270
  text "GND" at 79.2,106 h1.14 r270
  text "OSHW - CERN-OHL-S v2.0 /  github.com/austinp0573/Hardware /  " at 99.4,76.2 h1.5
